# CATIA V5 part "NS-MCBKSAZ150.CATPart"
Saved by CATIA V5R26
Part number: NS-MCBKSAZ150
Bounding box of the stored display mesh (mm): x -99.1 to 99.1, y 0 to 198, z -49.9 to 49.9
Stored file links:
  R:\Document\坂尻\その他\ナベヤデータ変換\安全カバーキャスター\MCBKSAZ150\NS-MCBKSAZ150.CATPart
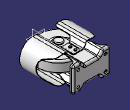
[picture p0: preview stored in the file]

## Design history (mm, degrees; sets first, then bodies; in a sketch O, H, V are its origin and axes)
Body1 (main body)
  Solid1: solid without history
